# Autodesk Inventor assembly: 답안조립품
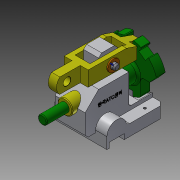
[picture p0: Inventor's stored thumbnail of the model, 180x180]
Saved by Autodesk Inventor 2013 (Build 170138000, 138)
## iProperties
Created: 2016-11
Part Number: 답안조립품
Document SubType Name: Assembly
Designer: cad22
Author: cad22
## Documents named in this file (8)
- C:\Documents and Settings\cad22\바탕 화면\461108V1011\답안조립품.iam
- C:\Documents and Settings\cad22\바탕 화면\461108V1011\1-본체.ipt
- C:\Documents and Settings\cad22\바탕 화면\461108V1011\부시.ipt
- C:\Documents and Settings\cad22\바탕 화면\461108V1011\분할축.ipt
- C:\Documents and Settings\cad22\바탕 화면\461108V1011\분할대.ipt
- C:\Documents and Settings\cad22\바탕 화면\461108V1011\클레비스핀.ipt
- C:\Documents and Settings\cad22\바탕 화면\461108V1011\와셔.ipt
- C:\Documents and Settings\cad22\바탕 화면\461108V1011\원통형핀.ipt
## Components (1 placed, 1 different names)
1. 1-본체:1
